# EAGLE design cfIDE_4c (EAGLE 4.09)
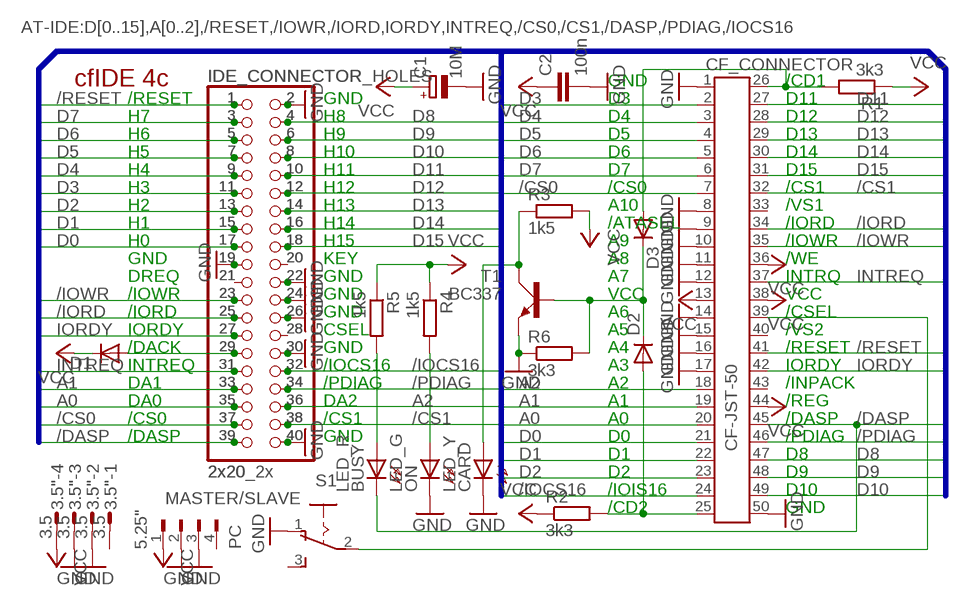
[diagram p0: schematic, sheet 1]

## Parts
3.5"  3.5  L04P  [L04P]
5.25"  PC  POWER-5.25  [POWER-5.25]
BUSY  LED_R  LED3MM  [LED3MM]
C1  10M  CPOL-EUE2-5  [E2-5]
C2  100n  C-EU050-024X044  [C050-024X044]
CARD  LED_Y  LED3MM  [LED3MM]
CF_CONNECTOR  CF-JST-50  [ICM-MA50H-SS52-1171]
D1  DIODE-D-5  [D-5]
D2  DIODE-D-5  [D-5]
D3  DIODE-D-5  [D-5]
IDE_CONNECTOR  2x20_2x  PINHD-2X20  [2X20]
IDE_CONNECTOR_HOLES  2x20  PINHD-2X20  [2X20]
ON  LED_G  LED3MM  [LED3MM]
R1  3k3  R-EU_0207/10  [0207/10]
R2  3k3  R-EU_0207/10  [0207/10]
R3  1k5  R-EU_0207/10  [0207/10]
R4  1k5  R-EU_0207/10  [0207/10]
R5  1k5  R-EU_0207/10  [0207/10]
R6  3k3  R-EU_0207/10  [0207/10]
S1  MASTER/SLAVE  255SB  [255SB]
T1  BC337  [SOT54A]

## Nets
/CS0: CF_CONNECTOR.7 IDE_CONNECTOR.37 IDE_CONNECTOR_HOLES.37
/CS1: CF_CONNECTOR.32 IDE_CONNECTOR.38 IDE_CONNECTOR_HOLES.38
/DASP: BUSY.K(C) CF_CONNECTOR.45 IDE_CONNECTOR.39 IDE_CONNECTOR_HOLES.39
/IOCS16: CF_CONNECTOR.24 IDE_CONNECTOR.32 IDE_CONNECTOR_HOLES.32
/IORD: CF_CONNECTOR.34 IDE_CONNECTOR.25 IDE_CONNECTOR_HOLES.25
/IOWR: CF_CONNECTOR.35 IDE_CONNECTOR.23 IDE_CONNECTOR_HOLES.23
/PDIAG: CF_CONNECTOR.46 IDE_CONNECTOR.34 IDE_CONNECTOR_HOLES.34
/RESET: CF_CONNECTOR.41 IDE_CONNECTOR.1 IDE_CONNECTOR_HOLES.1
A0: CF_CONNECTOR.20 IDE_CONNECTOR.35 IDE_CONNECTOR_HOLES.35
A1: CF_CONNECTOR.19 IDE_CONNECTOR.33 IDE_CONNECTOR_HOLES.33
A2: CF_CONNECTOR.18 IDE_CONNECTOR.36 IDE_CONNECTOR_HOLES.36
D0: CF_CONNECTOR.21 IDE_CONNECTOR.17 IDE_CONNECTOR_HOLES.17
D1: CF_CONNECTOR.22 IDE_CONNECTOR.15 IDE_CONNECTOR_HOLES.15
D2: CF_CONNECTOR.23 IDE_CONNECTOR.13 IDE_CONNECTOR_HOLES.13
D3: CF_CONNECTOR.2 IDE_CONNECTOR.11 IDE_CONNECTOR_HOLES.11
D4: CF_CONNECTOR.3 IDE_CONNECTOR.9 IDE_CONNECTOR_HOLES.9
D5: CF_CONNECTOR.4 IDE_CONNECTOR.7 IDE_CONNECTOR_HOLES.7
D6: CF_CONNECTOR.5 IDE_CONNECTOR.5 IDE_CONNECTOR_HOLES.5
D7: CF_CONNECTOR.6 IDE_CONNECTOR.3 IDE_CONNECTOR_HOLES.3
D8: CF_CONNECTOR.47 IDE_CONNECTOR.4 IDE_CONNECTOR_HOLES.4
D9: CF_CONNECTOR.48 IDE_CONNECTOR.6 IDE_CONNECTOR_HOLES.6
D10: CF_CONNECTOR.49 IDE_CONNECTOR.8 IDE_CONNECTOR_HOLES.8
D11: CF_CONNECTOR.27 IDE_CONNECTOR.10 IDE_CONNECTOR_HOLES.10
D12: CF_CONNECTOR.28 IDE_CONNECTOR.12 IDE_CONNECTOR_HOLES.12
D13: CF_CONNECTOR.29 IDE_CONNECTOR.14 IDE_CONNECTOR_HOLES.14
D14: CF_CONNECTOR.30 IDE_CONNECTOR.16 IDE_CONNECTOR_HOLES.16
D15: CF_CONNECTOR.31 IDE_CONNECTOR.18 IDE_CONNECTOR_HOLES.18
GND: 3.5".2 3.5".3 5.25".2 5.25".3 C1.- C2.2 CARD.K(C) CF_CONNECTOR.1 CF_CONNECTOR.8 CF_CONNECTOR.9 CF_CONNECTOR.10 CF_CONNECTOR.11 CF_CONNECTOR.12 CF_CONNECTOR.14 CF_CONNECTOR.15 CF_CONNECTOR.16 CF_CONNECTOR.17 CF_CONNECTOR.50 IDE_CONNECTOR.2 IDE_CONNECTOR.19 IDE_CONNECTOR.22 IDE_CONNECTOR.24 IDE_CONNECTOR.26 IDE_CONNECTOR.30 IDE_CONNECTOR.40 IDE_CONNECTOR_HOLES.2 IDE_CONNECTOR_HOLES.19 IDE_CONNECTOR_HOLES.22 IDE_CONNECTOR_HOLES.24 IDE_CONNECTOR_HOLES.26 IDE_CONNECTOR_HOLES.30 IDE_CONNECTOR_HOLES.40 ON.K(C) R6.1 S1.1(O) T1.E
INTREQ: CF_CONNECTOR.37 IDE_CONNECTOR.31 IDE_CONNECTOR_HOLES.31
IORDY: CF_CONNECTOR.42 IDE_CONNECTOR.27 IDE_CONNECTOR_HOLES.27
N$1: CARD.A R3.1 T1.C
N$2: ON.A R4.2
N$3: IDE_CONNECTOR.20 IDE_CONNECTOR_HOLES.20
N$4: IDE_CONNECTOR.21 IDE_CONNECTOR_HOLES.21
N$5: CF_CONNECTOR.25 D2.A R2.2
N$6: BUSY.A R5.2
N$8: IDE_CONNECTOR.28 IDE_CONNECTOR_HOLES.28
N$9: D1.A IDE_CONNECTOR.29 IDE_CONNECTOR_HOLES.29
N$10: CF_CONNECTOR.26 D3.A R1.2
N$11: D2.C D3.C R6.2 T1.B
N$12: CF_CONNECTOR.39 S1.2(P)
VCC: 3.5".4 5.25".1 C1.+ C2.1 CF_CONNECTOR.13 CF_CONNECTOR.36 CF_CONNECTOR.38 CF_CONNECTOR.44 D1.C R1.1 R2.1 R3.2 R4.1 R5.1
Unconnected: 3.5".1 5.25".4 CF_CONNECTOR.33 CF_CONNECTOR.40 CF_CONNECTOR.43 S1.3(S)

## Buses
AT-IDE:D[0..15],A[0..2],/RESET,/IOWR,/IORD,IORDY,INTREQ,/CS0,/CS1,/DASP,/PDIAG,/IOCS16

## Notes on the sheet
- cfIDE 4c | GND | /CD1
- /RESET | GND | D3 | D11
- H7 | H8 | D4 | D12
- H6 | H9 | D5 | D13
- H5 | H10 | D6 | D14
- H4 | H11 | D7 | D15
- H3 | H12 | /CS0 | /CS1
- H2 | H13 | A10 | /VS1
- H1 | H14 | /ATASEL | /IORD
- H0 | H15 | A9 | /IOWR
- GND | KEY | A8 | /WE
- DREQ | GND | A7 | INTRQ
- /IOWR | GND | VCC | VCC
- /IORD | GND | A6 | /CSEL
- IORDY | CSEL | A5 | /VS2
- /DACK | GND | A4 | /RESET
- INTREQ | /IOCS16 | A3 | IORDY
- DA1 | /PDIAG | A2 | /INPACK
- DA0 | DA2 | A1 | /REG
- /CS0 | /CS1 | A0 | /DASP
- /DASP | GND | D0 | /PDIAG
- D1 | D8
- D2 | D9
- /IOIS16 | D10
- /CD2 | GND

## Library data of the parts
3.5" = con-amp-mt:L04P: AMP MT CONNECTOR
5.25" = development:POWER-5.25: 5.25" PC power connector male
BUSY CARD ON = led:LED: LED
C1 = rcl:CPOL-EU: POLARIZED CAPACITOR, European symbol
C2 = rcl:C-EU: CAPACITOR, European symbol
CF_CONNECTOR = development:CF-JST-50: JST CompactFlash connector ICM-MA50H-SS52-1171
D1-D3 = diode:DIODE-: DIODE
IDE_CONNECTOR IDE_CONNECTOR_HOLES = pinhead:PINHD-2X20: PIN HEADER
R1-R6 = rcl:R-EU_: RESISTOR, European symbol
S1 = switch:255SB: SLIDING SWITCH distributor Buerklin, 11G810
T1 = transistor-small-signal:BC337: NPN TRANSISTOR

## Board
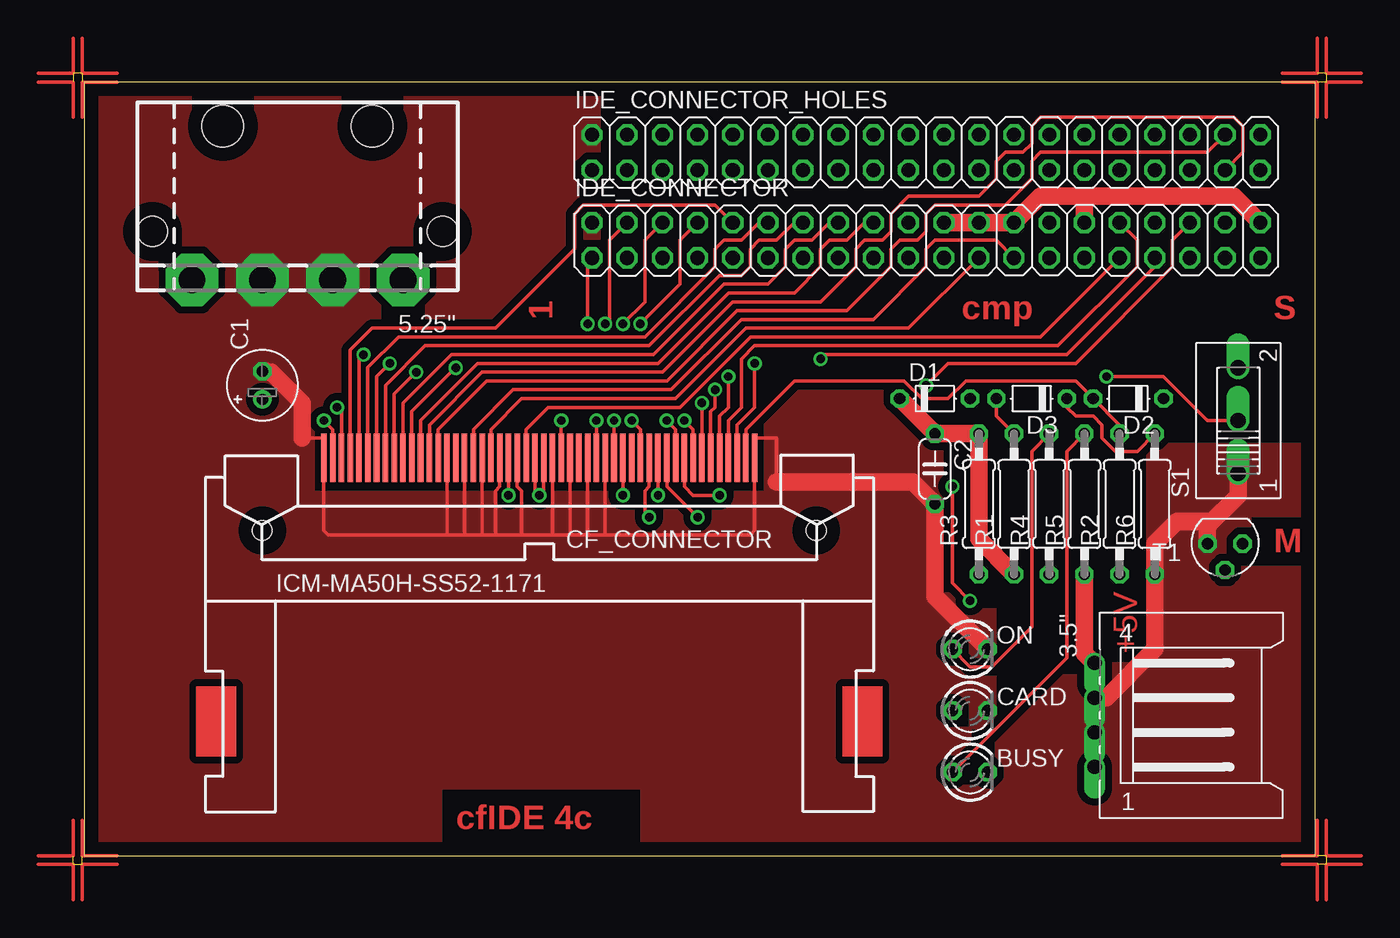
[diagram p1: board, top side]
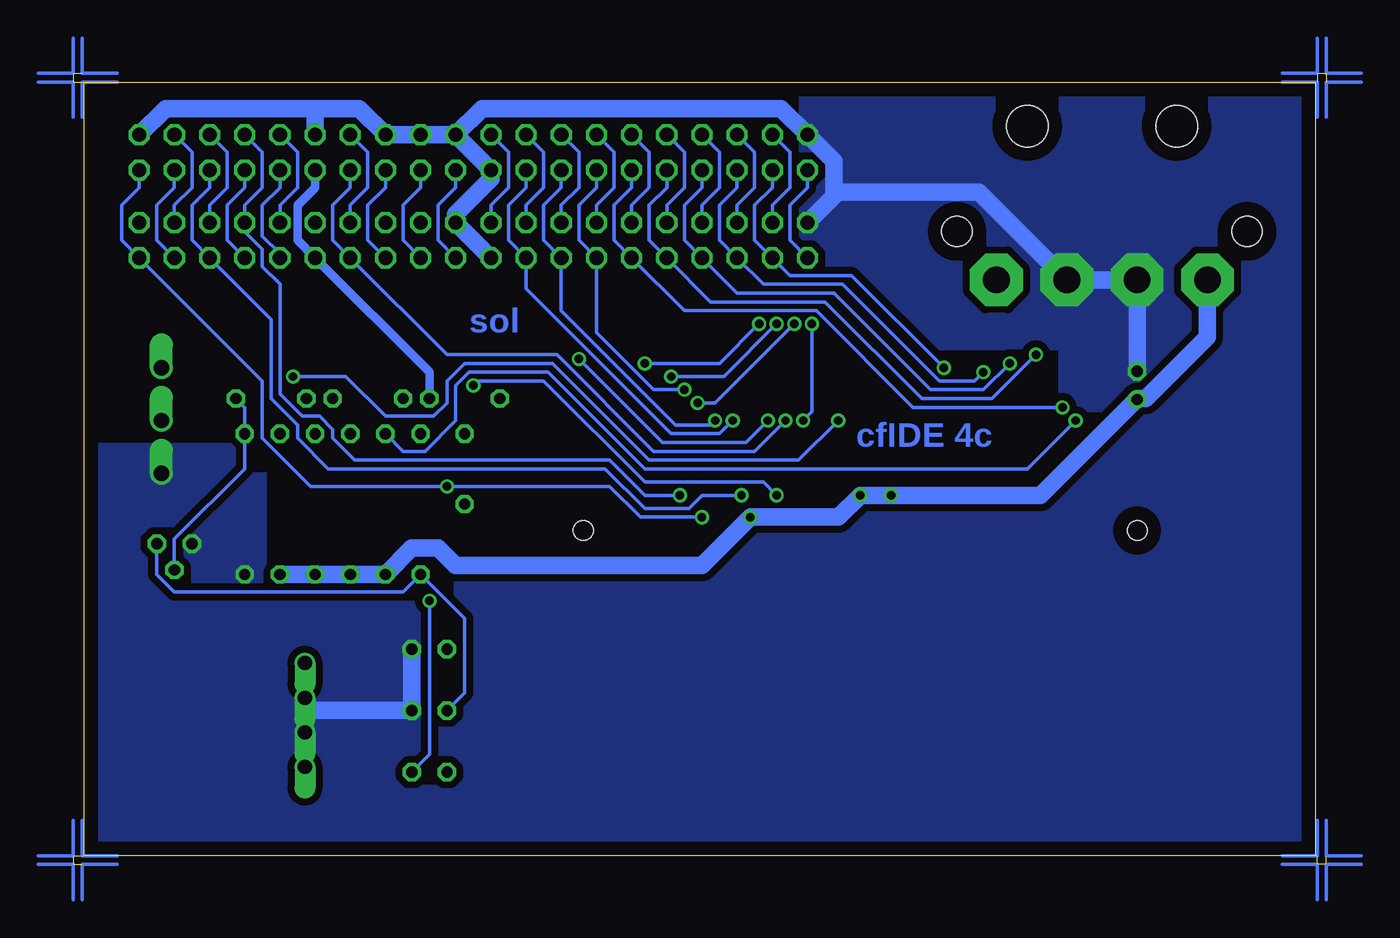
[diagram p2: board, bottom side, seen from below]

Size 88.89 x 55.87 mm. Coordinates in mm from the lower left corner, seen from the top.
Outline: 0,0 88.89,0 88.89,55.87 0,55.87 0,0
Copper layers used: Top, Bottom

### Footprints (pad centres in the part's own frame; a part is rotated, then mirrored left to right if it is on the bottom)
L04P = drill 1.016 offset: 1 3.75,-6.25; 2 1.25,-6.25; 3 -1.25,-6.25; 4 -3.75,-6.25
POWER-5.25 = drill 1.93 pad 3.81 octagon: 1 -9.842,-1.587; 2 -4.763,-1.587; 3 0.318,-1.587; 4 5.397,-1.587 | hole 2.184: -12.7,1.905; 8.255,1.905 | hole 3: -7.62,9.525; 3.175,9.525
LED3MM = drill 0.813 octagon: A -1.27,0; K 1.27,0
E2-5 = drill 0.813 pad 1.27 round: + -1.016,0 | drill 0.813 pad 1.27 octagon: - 1.016,0
C050-024X044 = drill 0.813 octagon: 1 -2.54,0; 2 2.54,0
ICM-MA50H-SS52-1171 = smd 0.4 x 3.5: 1 -15.557,7.795; 2 -14.287,7.795; 3 -13.018,7.795; 4 -11.748,7.795; 5 -10.477,7.795; 6 -9.207,7.795; 7 -7.938,7.795; 8 -6.668,7.795; 9 -5.397,7.795; 10 -4.128,7.795; 11 -2.857,7.795; 12 -1.587,7.795; 13 -0.318,7.795; 14 0.953,7.795; 15 2.223,7.795; 16 3.493,7.795; 17 4.763,7.795; 18 6.032,7.795; 19 7.303,7.795; 20 8.572,7.795; 21 9.842,7.795; 22 11.113,7.795; 23 12.383,7.795; 24 13.652,7.795; 25 14.922,7.795; 26 -14.922,7.795; 27 -13.652,7.795; 28 -12.383,7.795; 29 -11.113,7.795; 30 -9.842,7.795; 31 -8.572,7.795; 32 -7.303,7.795; 33 -6.032,7.795; 34 -4.763,7.795; 35 -3.493,7.795; 36 -2.223,7.795; 37 -0.953,7.795; 38 0.318,7.795; 39 1.587,7.795; 40 2.857,7.795; 41 4.128,7.795; 42 5.397,7.795; 43 6.668,7.795; 44 7.938,7.795; 45 9.207,7.795; 46 10.477,7.795; 47 11.748,7.795; 48 13.018,7.795; 49 14.287,7.795; 50 15.557,7.795 | hole 1.422: -20.003,2.54; 20.003,2.54
D-5 = drill 0.813 octagon: A 2.54,0; C -2.54,0
2X20 = drill 1.016 octagon: 1 -24.13,-1.27; 2 -24.13,1.27; 3 -21.59,-1.27; 4 -21.59,1.27; 5 -19.05,-1.27; 6 -19.05,1.27; 7 -16.51,-1.27; 8 -16.51,1.27; 9 -13.97,-1.27; 10 -13.97,1.27; 11 -11.43,-1.27; 12 -11.43,1.27; 13 -8.89,-1.27; 14 -8.89,1.27; 15 -6.35,-1.27; 16 -6.35,1.27; 17 -3.81,-1.27; 18 -3.81,1.27; 19 -1.27,-1.27; 20 -1.27,1.27; 21 1.27,-1.27; 22 1.27,1.27; 23 3.81,-1.27; 24 3.81,1.27; 25 6.35,-1.27; 26 6.35,1.27; 27 8.89,-1.27; 28 8.89,1.27; 29 11.43,-1.27; 30 11.43,1.27; 31 13.97,-1.27; 32 13.97,1.27; 33 16.51,-1.27; 34 16.51,1.27; 35 19.05,-1.27; 36 19.05,1.27; 37 21.59,-1.27; 38 21.59,1.27; 39 24.13,-1.27; 40 24.13,1.27
0207/10 = drill 0.813 octagon: 1 -5.08,0; 2 5.08,0
255SB = drill 1.118 offset: 1 -3.81,0; 2 0,0; 3 3.81,0
SOT54A = drill 0.813 octagon: B 0,1.905; C -1.27,0; E 1.27,0

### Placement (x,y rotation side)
3.5"  79.21,10.16 270 top
5.25"  17.61,43.18 0 top
BUSY  63.97,6.03 0 top
C1  12.85,33.97 90 top
C2  61.43,27.93 270 top
CARD  63.97,10.47 0 top
CF_CONNECTOR  32.85,20.95 0 top
D1  61.43,33.02 0 top
D2  75.4,33.02 180 top
D3  68.41,33.02 180 top
IDE_CONNECTOR  60.8,44.45 0 top
IDE_CONNECTOR_HOLES  60.8,50.8 0 top
ON  63.97,14.92 0 top
R1  67.14,25.39 90 top
R2  74.77,25.39 90 top
R3  64.61,25.39 90 top
R4  69.69,25.39 90 top
R5  72.22,25.39 90 top
R6  77.3,25.39 90 top
S1  83.34,31.43 90 top
T1  82.39,22.54 180 top

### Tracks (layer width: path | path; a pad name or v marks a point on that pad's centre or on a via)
/CS0
  Top 0.254: IDE_CONNECTOR_HOLES.37 83.66,50.8 83.66,52.7 83.02,53.34 69.05,53.34 68.41,52.7 68.41,51.43 67.78,50.8 66.51,50.8 65.88,50.16 65.88,48.89 64.61,47.62 59.52,47.62 58.25,46.35 58.25,45.08 57.62,44.45 56.35,44.45 55.71,43.81 55.71,42.54 53.17,40 46.82,40 41.74,34.92 28.73,34.92 24.92,31.11 CF_CONNECTOR.7
  Bottom 0.254: IDE_CONNECTOR.37 83.66,44.45 83.66,46.98 82.39,48.26 IDE_CONNECTOR_HOLES.37
/CS1
  Top 0.254: IDE_CONNECTOR_HOLES.38 81.11,50.8 69.05,50.8 68.41,50.16 68.41,48.89 66.51,46.98 61.43,46.98 60.8,46.35 60.8,45.08 60.16,44.45 58.89,44.45 58.25,43.81 58.25,42.54 55.08,39.37 47.14,39.37 42.06,34.29 29.04,34.29 25.55,30.79 CF_CONNECTOR.32
  Bottom 0.254: IDE_CONNECTOR_HOLES.38 81.11,50.8 81.11,48.26 82.39,46.98 IDE_CONNECTOR.38
/DASP  (via drill 0.61)
  Top 0.254: v44.28,24.44 42.06,26.66 CF_CONNECTOR.45 | v63.97,18.41 62.7,19.68 v62.7,26.66
  Bottom 0.254: IDE_CONNECTOR_HOLES.39 84.92,48.26 86.19,46.98 86.19,44.45 IDE_CONNECTOR.39 76.03,34.29 76.03,30.16 72.54,26.66 v62.7,26.66 50.95,26.66 48.73,24.44 v44.28,24.44 | BUSY.K 63.97,7.3 v63.97,18.41
/IOCS16
  Top 0.254: IDE_CONNECTOR.32 76.03,44.45 76.03,42.54 70.32,36.83 48.41,36.83 47.46,35.87 47.46,32.38 46.51,31.43 CF_CONNECTOR.24
  Bottom 0.254: IDE_CONNECTOR_HOLES.32 73.5,50.8 73.5,48.26 74.77,46.98 IDE_CONNECTOR.32
/IORD
  Top 0.254: IDE_CONNECTOR.25 65.88,44.45 61.43,44.45 60.8,43.81 60.8,42.54 56.98,38.73 47.46,38.73 42.38,33.65 30.95,33.65 28.09,30.79 CF_CONNECTOR.34 28.09,28.57
  Bottom 0.254: IDE_CONNECTOR_HOLES.25 67.14,48.26 68.41,46.98 68.41,44.45 IDE_CONNECTOR.25
/IOWR
  Top 0.254: IDE_CONNECTOR.23 59.52,38.1 47.78,38.1 42.7,33.02 31.58,33.02 29.36,30.79 CF_CONNECTOR.35
  Bottom 0.254: IDE_CONNECTOR_HOLES.23 64.61,48.26 65.88,46.98 65.88,44.45 IDE_CONNECTOR.23
/PDIAG  (via drill 0.61)
  Top 0.254: v45.87,26.03 43.97,26.03 43.33,26.66 CF_CONNECTOR.46
  Bottom 0.254: IDE_CONNECTOR_HOLES.34 76.03,50.8 76.03,48.26 77.3,46.98 IDE_CONNECTOR.34 77.3,45.08 76.03,43.81 76.03,42.54 74.77,41.27 74.77,33.33 73.18,31.74 71.91,31.74 70.95,30.79 70.95,30.16 69.37,28.57 50.95,28.57 48.41,26.03 v45.87,26.03
/RESET  (via drill 0.61)
  Top 0.254: v36.35,38.41 36.35,42.86 IDE_CONNECTOR.1 | CF_CONNECTOR.41 v36.98,31.43
  Bottom 0.254: IDE_CONNECTOR.1 37.94,44.45 37.94,46.98 36.66,48.26 IDE_CONNECTOR_HOLES.1 | v36.98,31.43 36.35,32.06 v36.35,38.41
A0  (via drill 0.61)
  Top 0.254: v41.43,26.03 CF_CONNECTOR.20
  Bottom 0.254: IDE_CONNECTOR_HOLES.35 79.84,48.26 81.11,46.98 81.11,44.45 IDE_CONNECTOR.35 75.4,38.73 75.4,33.02 73.5,31.11 73.5,30.16 71.27,27.93 51.27,27.93 48.41,25.08 45.24,25.08 44.28,26.03 v41.43,26.03
A1  (via drill 0.61)
  Top 0.254: v39.52,31.43 40.16,30.79 CF_CONNECTOR.19 | IDE_CONNECTOR.33 77.3,42.54 70.95,36.19 53.49,36.19 v53.17,35.87
  Bottom 0.254: IDE_CONNECTOR.33 78.58,44.45 78.58,46.98 77.3,48.26 IDE_CONNECTOR_HOLES.33 | v39.52,31.43 41.11,29.84 47.14,29.84 v53.17,35.87
A2  (via drill 0.61)
  Top 0.254: v60.8,33.97 62.38,35.55 71.59,35.55 78.58,42.54 78.58,44.45 IDE_CONNECTOR.36 | v38.89,26.03 CF_CONNECTOR.18
  Bottom 0.254: IDE_CONNECTOR_HOLES.36 78.58,50.8 78.58,48.26 79.84,46.98 IDE_CONNECTOR.36 | v38.89,26.03 39.84,26.98 48.41,26.98 55.71,34.29 60.48,34.29 v60.8,33.97
D0  (via drill 0.61)
  Top 0.254: v42.06,31.43 42.7,30.79 CF_CONNECTOR.21 42.7,28.57
  Bottom 0.254: IDE_CONNECTOR_HOLES.17 56.98,48.26 58.25,46.98 58.25,44.45 IDE_CONNECTOR.17 56.98,40.95 46.51,30.47 43.02,30.47 v42.06,31.43
D1  (via drill 0.61)
  Top 0.254: v43.33,31.43 43.97,30.79 CF_CONNECTOR.22
  Bottom 0.254: IDE_CONNECTOR_HOLES.15 54.45,48.26 55.71,46.98 55.71,44.45 IDE_CONNECTOR.15 54.45,39.37 46.19,31.11 43.65,31.11 v43.33,31.43
D2  (via drill 0.61)
  Top 0.254: v45.55,33.65 45.55,32.38 45.24,32.06 CF_CONNECTOR.23
  Bottom 0.254: IDE_CONNECTOR_HOLES.13 51.91,48.26 53.17,46.98 53.17,44.45 IDE_CONNECTOR.13 51.91,37.78 47.78,33.65 v45.55,33.65
D3  (via drill 0.61)
  Top 0.254: v18.25,32.38 18.57,32.06 CF_CONNECTOR.2
  Bottom 0.254: IDE_CONNECTOR_HOLES.11 49.37,48.26 50.63,46.98 50.63,44.45 IDE_CONNECTOR.11 45.55,39.37 36.03,39.37 29.04,32.38 v18.25,32.38
D4  (via drill 0.61)
  Top 0.254: v20.15,36.19 19.84,35.87 CF_CONNECTOR.3
  Bottom 0.254: IDE_CONNECTOR_HOLES.9 46.82,48.26 48.09,46.98 48.09,44.45 IDE_CONNECTOR.9 43.65,40 35.39,40 28.41,33.02 23.33,33.02 v20.15,36.19
D5  (via drill 0.61)
  Top 0.254: v22.06,35.55 21.11,34.6 CF_CONNECTOR.4
  Bottom 0.254: IDE_CONNECTOR_HOLES.7 44.28,48.26 45.55,46.98 45.55,44.45 IDE_CONNECTOR.7 41.74,40.64 34.76,40.64 27.77,33.65 23.96,33.65 v22.06,35.55
D6  (via drill 0.61)
  Top 0.254: v23.96,34.92 22.38,33.33 CF_CONNECTOR.5
  Bottom 0.254: IDE_CONNECTOR_HOLES.5 41.74,48.26 43.02,46.98 43.02,44.45 IDE_CONNECTOR.5 39.84,41.27 34.12,41.27 27.14,34.29 24.6,34.29 v23.96,34.92
D7  (via drill 0.61)
  Top 0.254: v26.82,35.24 23.65,32.06 CF_CONNECTOR.6
  Bottom 0.254: IDE_CONNECTOR_HOLES.3 39.2,48.26 40.48,46.98 40.48,44.45 IDE_CONNECTOR.3 37.94,41.91 33.49,41.91 v26.82,35.24
D8  (via drill 0.61)
  Top 0.254: 44.6,30.16 44.6,30.47 | 44.6,30.16 v44.6,32.7 | v37.62,38.41 37.94,38.73 37.94,44.45 IDE_CONNECTOR.4 | CF_CONNECTOR.47 44.6,30.16
  Bottom 0.254: IDE_CONNECTOR_HOLES.4 37.94,50.8 37.94,48.26 39.2,46.98 IDE_CONNECTOR.4 | v44.6,32.7 43.33,32.7 v37.62,38.41
D9  (via drill 0.61)
  Top 0.254: v46.51,34.6 46.51,32.38 45.87,31.74 CF_CONNECTOR.48 | v38.89,38.41 40.48,40 40.48,44.45 IDE_CONNECTOR.6
  Bottom 0.254: IDE_CONNECTOR_HOLES.6 40.48,50.8 40.48,48.26 41.74,46.98 IDE_CONNECTOR.6 | v46.51,34.6 42.7,34.6 v38.89,38.41
D10  (via drill 0.61)
  Top 0.254: v40.16,38.41 43.02,41.27 43.02,44.45 IDE_CONNECTOR.8 | v48.41,35.55 48.41,32.38 47.14,31.11 CF_CONNECTOR.49
  Bottom 0.254: IDE_CONNECTOR_HOLES.8 43.02,50.8 43.02,48.26 44.28,46.98 IDE_CONNECTOR.8 | v48.41,35.55 43.02,35.55 v40.16,38.41
D11
  Top 0.254: IDE_CONNECTOR.10 45.55,46.98 36.03,46.98 35.39,46.35 35.39,43.81 29.68,38.1 20.79,38.1 19.2,36.51 CF_CONNECTOR.27
  Bottom 0.254: IDE_CONNECTOR_HOLES.10 45.55,50.8 45.55,48.26 46.82,46.98 IDE_CONNECTOR.10
D12
  Top 0.254: IDE_CONNECTOR.12 48.73,45.72 47.46,44.45 46.19,44.45 45.55,43.81 45.55,42.54 40.48,37.46 22.7,37.46 20.47,35.24 CF_CONNECTOR.28
  Bottom 0.254: IDE_CONNECTOR_HOLES.12 48.09,50.8 48.09,48.26 49.37,46.98 IDE_CONNECTOR.12
D13
  Top 0.254: IDE_CONNECTOR.14 51.27,45.72 50,44.45 48.73,44.45 48.09,43.81 48.09,42.54 47.46,41.91 45.87,41.91 40.79,36.83 24.6,36.83 21.74,33.97 CF_CONNECTOR.29
  Bottom 0.254: IDE_CONNECTOR_HOLES.14 50.63,50.8 50.63,48.26 51.91,46.98 IDE_CONNECTOR.14
D14
  Top 0.254: IDE_CONNECTOR.16 53.81,45.72 52.54,44.45 51.27,44.45 50.63,43.81 50.63,42.54 49.37,41.27 46.19,41.27 41.11,36.19 26.5,36.19 23.01,32.7 CF_CONNECTOR.30
  Bottom 0.254: IDE_CONNECTOR_HOLES.16 53.17,50.8 53.17,48.26 54.45,46.98 IDE_CONNECTOR.16
D15
  Top 0.254: IDE_CONNECTOR.18 56.35,45.72 55.08,44.45 53.81,44.45 53.17,43.81 53.17,42.54 51.27,40.64 46.51,40.64 41.43,35.55 28.41,35.55 24.28,31.43 CF_CONNECTOR.31
  Bottom 0.254: IDE_CONNECTOR_HOLES.18 55.71,50.8 55.71,48.26 56.98,46.98 IDE_CONNECTOR.18
GND
  Top 0.254: 26.19,23.17 17.61,23.17 17.3,23.49 CF_CONNECTOR.1 17.3,30.16 15.71,30.16 | 26.19,23.17 27.46,23.17 | 27.46,23.17 28.73,23.17 | 28.73,23.17 29.68,23.17 | 29.68,23.17 31.58,23.17 | 31.58,23.17 33.81,23.17 | 33.81,23.17 35.08,23.17 | 35.08,23.17 36.35,23.17 | 36.35,23.17 37.62,23.17 | 37.62,23.17 48.09,23.17 48.41,23.49 48.41,26.98 | 29.68,23.17 29.68,26.35 30,26.66 CF_CONNECTOR.11 | 31.58,23.17 31.58,26.35 31.27,26.66 CF_CONNECTOR.12 31.27,28.89 | 48.41,26.98 48.41,30.16 50,30.16 50,26.98 | 27.46,23.17 CF_CONNECTOR.9 | 26.19,23.17 CF_CONNECTOR.8 | 28.73,23.17 CF_CONNECTOR.10 | 36.35,23.17 CF_CONNECTOR.16 | 35.08,23.17 CF_CONNECTOR.15 | 33.81,23.17 CF_CONNECTOR.14 | 37.62,23.17 CF_CONNECTOR.17 | 48.41,26.98 CF_CONNECTOR.50
  Top 1.27: IDE_CONNECTOR.40 83.02,47.62 72.22,47.62 | 72.22,47.62 69.05,47.62 IDE_CONNECTOR.26 IDE_CONNECTOR.24 IDE_CONNECTOR.22 | 72.22,47.62 IDE_CONNECTOR.30 | ON.K 61.43,18.73 C2.2 59.84,26.98 50,26.98 | 81.11,23.81 81.11,24.12 78.89,24.12 77.3,22.54 R6.1 77.3,14.92 73.79,11.41 3.5".3 | 81.11,23.81 T1.E | S1.1 83.34,26.03 81.11,23.81 | 15.71,30.16 15.71,32.7 13.49,34.92 13.17,34.92 13.11,34.98 C1.-
  Bottom 1.27: IDE_CONNECTOR_HOLES.22 IDE_CONNECTOR_HOLES.24 IDE_CONNECTOR_HOLES.26 69.05,53.97 72.22,53.97 | 72.22,53.97 83.02,53.97 IDE_CONNECTOR_HOLES.40 | 72.22,53.97 IDE_CONNECTOR_HOLES.30 | IDE_CONNECTOR_HOLES.22 IDE_CONNECTOR_HOLES.19 59.52,48.89 62.06,46.35 IDE_CONNECTOR.22 IDE_CONNECTOR.19 | 34.76,47.94 34.76,50.16 IDE_CONNECTOR_HOLES.2 38.57,53.97 60.16,53.97 IDE_CONNECTOR_HOLES.22 | 34.76,47.94 34.76,47.62 IDE_CONNECTOR.2 | ON.K CARD.K 72.86,10.47 72.86,11.43 | 72.86,11.43 72.88,11.41 | 72.88,11.41 3.5".3 72.86,11.41 72.86,11.43 | 3.5".2 72.96,11.33 72.88,11.41 | C1.- 5.25".2 5.25".3 24.28,47.94 34.76,47.94
  pour Bottom (isolate 0.508, no thermals): 36.66,55.88 0.15,55.88 0.15,-0.01 88.73,-0.01 88.73,29.2 76.35,29.2 76.35,20.95 45.24,20.95 45.24,27.93 17.93,27.93 17.93,37.14 36.66,37.14
  pour Top (isolate 0.508, no thermals): 36.66,55.88 36.66,37.46 19.52,37.46 19.52,32.06 16.03,32.06 16.03,25.71 49.68,25.71 49.68,33.65 61.43,33.65 61.43,18.41 65.24,18.41 65.24,7.93 70.64,13.33 77.3,13.33 77.3,29.2 88.73,29.2 88.73,25.08 83.66,25.08 83.66,20.31 88.73,20.31 88.73,0.31 40.79,0.31 40.79,5.39 25.23,5.39 25.23,0.31 0.15,0.31 0.15,55.88
INTREQ
  Top 0.254: IDE_CONNECTOR.31 69.05,37.46 48.09,37.46 43.02,32.38 33.49,32.38 31.9,30.79 CF_CONNECTOR.37 31.9,28.57
  Bottom 0.254: IDE_CONNECTOR_HOLES.31 74.77,48.26 76.03,46.98 76.03,44.76 74.77,43.49 IDE_CONNECTOR.31
IORDY  (via drill 0.61)
  Top 0.254: CF_CONNECTOR.42 v38.25,31.43
  Bottom 0.254: IDE_CONNECTOR_HOLES.27 69.69,48.26 70.95,46.98 70.95,44.45 IDE_CONNECTOR.27 62.7,36.19 54.76,36.19 47.78,29.2 40.48,29.2 v38.25,31.43
N$1
  Bottom 0.254: CARD.A 61.43,11.74 61.43,17.14 R3.1 65.88,19.04 82.39,19.04 83.66,20.31 T1.C
N$2
  Top 0.254: R4.2 68.41,29.2 68.41,16.5 65.56,13.65 63.97,13.65 ON.A
N$3
  Bottom 0.254: IDE_CONNECTOR_HOLES.20 58.25,50.8 58.25,48.26 59.52,46.98 IDE_CONNECTOR.20
N$4
  Bottom 0.254: IDE_CONNECTOR_HOLES.21 62.06,48.26 63.34,46.98 63.34,44.45 IDE_CONNECTOR.21
N$5
  Top 0.254: R2.2 74.77,31.11 D2.A 71.59,34.29 63.65,34.29 62.38,33.02 60.48,33.02 59.21,34.29 51.27,34.29 47.78,30.79 CF_CONNECTOR.25
N$6
  Top 0.254: R5.2 70.95,29.2 70.95,14.28 BUSY.A
N$7  (3 unrouted)
  Bottom 0.254: -0.17,53.34 -0.17,55.88 2.38,55.88 | -0.8,53.34 -0.8,55.88 -3.34,55.88 | 2.38,56.51 -0.17,56.51 -0.17,59.05 | -3.34,56.51 -0.8,56.51 -0.8,59.05
N$8
  Bottom 0.254: IDE_CONNECTOR.28 69.69,46.98 68.41,48.26 68.41,50.8 IDE_CONNECTOR_HOLES.28
N$9
  Bottom 0.61: IDE_CONNECTOR_HOLES.29 72.22,48.26 73.5,46.98 73.5,44.45 IDE_CONNECTOR.29 63.97,34.92 D1.A
N$10  (via drill 0.61)
  Top 0.254: v17.3,31.43 17.93,30.79 CF_CONNECTOR.26 17.93,28.57 | D3.A 65.88,31.74 R1.2
  Bottom 0.254: v17.3,31.43 20.79,27.93 48.41,27.93 55.4,34.92 61.11,34.92 62.06,33.97 62.06,31.43 64.29,29.2 65.88,29.2 R1.2
N$11
  Top 0.254: D3.C 70.95,32.38 71.59,31.74 72.86,31.74 73.5,31.11 73.5,30.16 74.45,29.2 76.03,29.2 R6.2
  Bottom 0.254: D2.C 77.3,32.38 R6.2 77.3,27.93 82.39,22.86 T1.B
N$12  (via drill 0.61)
  Top 0.254: v73.81,34.6 77.94,34.6 81.11,31.43 S1.2 | CF_CONNECTOR.39 v34.44,31.43
  Bottom 0.254: v34.44,31.43 37.3,28.57 48.09,28.57 55.08,35.55 61.43,35.55 62.7,34.29 62.7,32.7 63.65,31.74 67.14,31.74 70,34.6 v73.81,34.6
N$20  (3 unrouted)
  Bottom 0.254: -0.17,-3.18 -0.17,-0.64 2.38,-0.64 | -0.8,-3.18 -0.8,-0.64 -3.34,-0.64 | 2.38,-0.01 -0.17,-0.01 -0.17,2.54 | -3.34,-0.01 -0.8,-0.01 -0.8,2.54
N$21  (3 unrouted)
  Bottom 0.254: 89.69,53.34 89.69,55.88 92.23,55.88 | 89.05,53.34 89.05,55.88 86.51,55.88 | 92.23,56.51 89.69,56.51 89.69,59.05 | 86.51,56.51 89.05,56.51 89.05,59.05
N$22  (3 unrouted)
  Bottom 0.254: 92.23,-0.01 89.69,-0.01 89.69,2.54 | 92.23,-0.64 89.69,-0.64 89.69,-3.18 | 89.05,2.54 89.05,-0.01 86.51,-0.01 | 89.05,-3.18 89.05,-0.64 86.51,-0.64
N$23  (3 unrouted)
  Top 0.254: 89.69,53.34 89.69,55.88 92.23,55.88 | 89.05,53.34 89.05,55.88 86.51,55.88 | 92.23,56.51 89.69,56.51 89.69,59.05 | 86.51,56.51 89.05,56.51 89.05,59.05
N$24  (3 unrouted)
  Top 0.254: 92.23,-0.01 89.69,-0.01 89.69,2.54 | 92.23,-0.64 89.69,-0.64 89.69,-3.18 | 89.05,2.54 89.05,-0.01 86.51,-0.01 | 89.05,-3.18 89.05,-0.64 86.51,-0.64
N$25  (3 unrouted)
  Top 0.254: -0.17,53.34 -0.17,55.88 2.38,55.88 | -0.8,53.34 -0.8,55.88 -3.34,55.88 | 2.38,56.51 -0.17,56.51 -0.17,59.05 | -3.34,56.51 -0.8,56.51 -0.8,59.05
N$26  (3 unrouted)
  Top 0.254: -0.17,-3.18 -0.17,-0.64 2.38,-0.64 | -0.8,-3.18 -0.8,-0.64 -3.34,-0.64 | 2.38,-0.01 -0.17,-0.01 -0.17,2.54 | -3.34,-0.01 -0.8,-0.01 -0.8,2.54
VCC  (via drill 0.61)
  Top 0.254: v40.79,24.44 40.48,24.76 40.48,26.35 40.79,26.66 CF_CONNECTOR.44 | 32.54,28.89 CF_CONNECTOR.13 32.54,26.35 v32.85,26.03 33.17,26.35 CF_CONNECTOR.38 | v30.63,26.03 CF_CONNECTOR.36
  Top 1.27: D1.C C2.1 R3.2 64.61,22.86 R1.1 | 3.5".4 72.92,13.91 72.22,14.6 R5.1
  Bottom 1.27: 20.79,26.03 v30.63,26.03 v32.85,26.03 34.44,24.44 v40.79,24.44 44.28,20.95 62.06,20.95 63.34,22.22 65.24,22.22 R1.1 R4.1 R5.1 R2.1 | 20.79,26.03 20.73,26.03 | 20.79,26.03 19.84,26.03 12.92,32.95 C1.+ 12.85,33.02 12.22,33.02 7.77,37.46 5.25".1

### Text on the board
Top: 1 | cmp | S | M | +5V | cfIDE 4c
Bottom: sol | cfIDE 4c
